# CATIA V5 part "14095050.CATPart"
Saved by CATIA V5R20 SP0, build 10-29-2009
Part number: 14095050
Definition: NONE
Nomenclature: 14095050
Source: Unknown
Description: 14095050
Bounding box of the stored display mesh (mm): x -25 to 100, y -61.5 to 51.6, z -51.6 to 51.6
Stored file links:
  C:\Users\Utente\Desktop\IO LAVORO\3D X SITO CF\X SITO\PLASTICA\RF2\14095050.CATPart
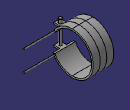
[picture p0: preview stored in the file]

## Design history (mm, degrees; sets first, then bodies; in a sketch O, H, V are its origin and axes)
Body1 "14095050" (main body)
  Solid1: solid without history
